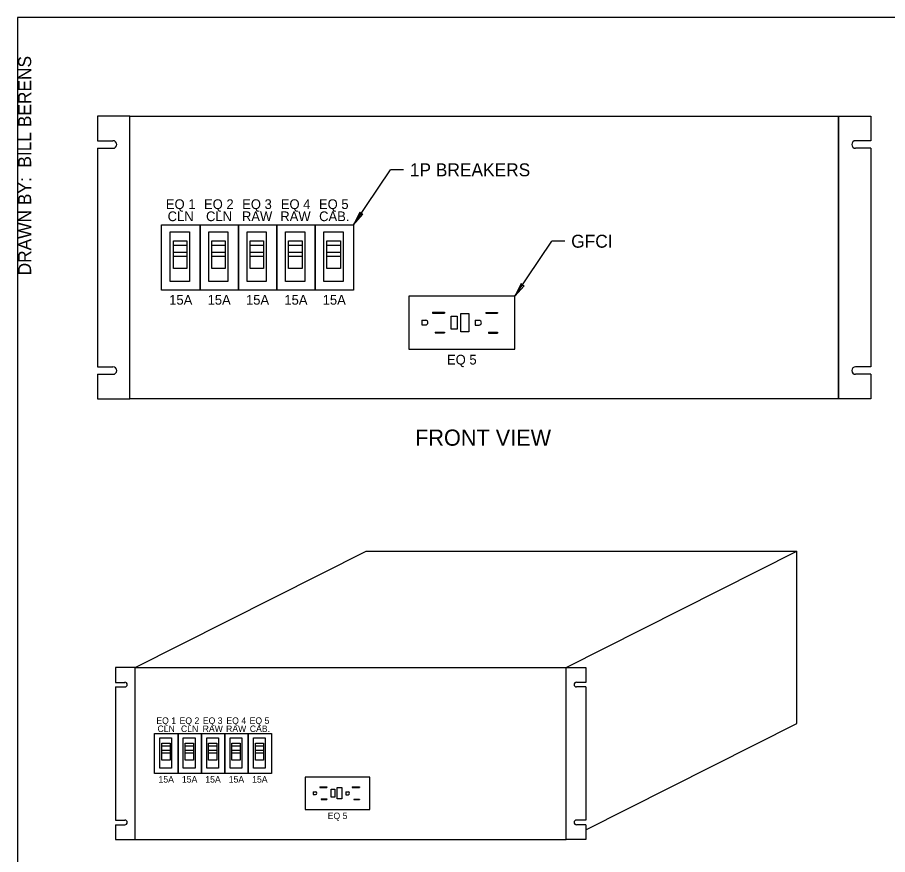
# Model space of a CAD drawing. Extents: x 99862 to 103680, y 99470 to 102076.
# Drawn here: x 99862 to 100936, y 101041 to 102076 of the extents above; entities that cross this region are included whole.
import ezdxf

# ---------------------------------------------------------------- set-up
doc = ezdxf.new("R2010")
doc.units = 0
for name, color, linetype in [('Level 1', 7, 'Continuous'), ('Level 11', 7, 'Continuous'), ('Level 15', 7, 'Continuous'), ('Level 2', 7, 'Continuous'), ('Level 20', 7, 'Continuous'), ('Level 26', 7, 'Continuous'), ('Level 40', 7, 'Continuous'), ('Level 62', 7, 'Continuous'), ('TR_TS_TrafficSystemsUserLevel2New', 7, 'Continuous')]:
    doc.layers.add(name, color=color, linetype=linetype)

msp = doc.modelspace()

# ---------------------------------------------------------------- linework, layer by layer
at = {"layer": 'Level 1'}
msp.add_lwpolyline([(99862, 99999.5), (103151, 99999.5), (103151, 102075.5), (99862, 102075.5)], close=True, dxfattribs=at)
at = {"layer": 'Level 11'}
for p, q in [((100374.5, 101711.3), (100389.1, 101711.3)), ((100374.5, 101711.3), (100374.5, 101710.1)), ((100374.5, 101710.1), (100389.1, 101710.1)), ((100389.1, 101711.3), (100389.1, 101710.1)), ((100440.2, 101711.1), (100454.8, 101711.1)), ((100440.2, 101711.1), (100440.2, 101710)), ((100440.2, 101710), (100454.8, 101710)), ((100454.8, 101711.1), (100454.8, 101710)), ((100361.4, 101701.4), (100361.4, 101695.6)), ((100361.4, 101701.4), (100366.2, 101701.4)), ((100427.2, 101701.3), (100427.2, 101695.4)), ((100427.2, 101701.3), (100431.9, 101701.3)), ((100361.4, 101695.6), (100366, 101695.6)), ((100377.8, 101686.8), (100389.2, 101686.8)), ((100377.8, 101686.8), (100377.8, 101685.7)), ((100389.2, 101686.8), (100389.2, 101685.7)), ((100427.2, 101695.4), (100431.9, 101695.4)), ((100443.5, 101686.7), (100454.9, 101686.7)), ((100443.5, 101686.7), (100443.5, 101685.5)), ((100454.9, 101686.7), (100454.9, 101685.5)), ((100377.8, 101685.7), (100389.2, 101685.7)), ((100443.5, 101685.5), (100454.9, 101685.5)), ((100227.3, 101118.9), (100227.3, 101115.4)), ((100227.3, 101118.9), (100230.2, 101118.9)), ((100235.2, 101125), (100244.2, 101125)), ((100235.2, 101125), (100235.2, 101124.3)), ((100235.2, 101124.3), (100244.2, 101124.3)), ((100244.2, 101125), (100244.2, 101124.3)), ((100267.3, 101118.9), (100267.3, 101115.3)), ((100267.3, 101118.9), (100270.2, 101118.9)), ((100275.3, 101124.9), (100284.2, 101124.9)), ((100275.3, 101124.9), (100275.3, 101124.2)), ((100275.3, 101124.2), (100284.2, 101124.2)), ((100284.2, 101124.9), (100284.2, 101124.2)), ((100227.3, 101115.4), (100230.1, 101115.4)), ((100237.2, 101110.1), (100244.2, 101110.1)), ((100237.2, 101110.1), (100237.2, 101109.4)), ((100237.2, 101109.4), (100244.2, 101109.4)), ((100244.2, 101110.1), (100244.2, 101109.4)), ((100267.3, 101115.3), (100270.3, 101115.3)), ((100277.3, 101110), (100284.3, 101110)), ((100277.3, 101110), (100277.3, 101109.3)), ((100277.3, 101109.3), (100284.3, 101109.3)), ((100284.3, 101110), (100284.3, 101109.3))]:
    msp.add_line(p, q, dxfattribs=at)
for centre, radius, start, end in [((100366, 101698.5), 2.91, 269.7062, 86.4581), ((100431.9, 101698.3), 2.9, 271.1491, 89.3526), ((100230.1, 101117.2), 1.77, 269.7062, 86.4581), ((100270.2, 101117.1), 1.77, 271.1491, 89.3526)]:
    msp.add_arc(centre, radius, start, end, dxfattribs=at)
at = {"layer": 'Level 15'}
for p, q in [((100277, 101819.3), (100322.5, 101887.2)), ((100338.5, 101887.2), (100322.5, 101887.2)), ((100476.2, 101731.1), (100521.7, 101799)), ((100537.7, 101799), (100521.7, 101799))]:
    msp.add_line(p, q, dxfattribs=at)
for points in [[(100277, 101819.3), (100288.4, 101832.3), (100286.1, 101832.9), (100284.7, 101834.8)], [(100476.2, 101731.1), (100487.6, 101744.1), (100485.3, 101744.7), (100483.9, 101746.6)]]:
    msp.add_lwpolyline(points, close=True, dxfattribs=at)
at = {"layer": 'Level 2'}
for p, q in [((100054.6, 101780.4), (100071.2, 101780.4)), ((100102, 101780.4), (100118.6, 101780.4)), ((100149.4, 101780.4), (100166, 101780.4)), ((100196.8, 101780.4), (100213.4, 101780.4)), ((100244.2, 101780.4), (100260.8, 101780.4)), ((100040.3, 101167.1), (100050.4, 101167.1)), ((100069.1, 101167.1), (100079.3, 101167.1)), ((100098, 101167.1), (100108.1, 101167.1)), ((100126.9, 101167.1), (100137, 101167.1)), ((100155.8, 101167.1), (100165.9, 101167.1))]:
    msp.add_line(p, q, dxfattribs=at)
for points in [[(100040.1, 101819.3), (100087.5, 101819.3), (100087.5, 101738.4), (100040.1, 101738.4)], [(100087.5, 101819.3), (100134.9, 101819.3), (100134.9, 101738.4), (100087.5, 101738.4)], [(100134.9, 101819.3), (100182.2, 101819.3), (100182.2, 101738.4), (100134.9, 101738.4)], [(100182.2, 101819.3), (100229.6, 101819.3), (100229.6, 101738.4), (100182.2, 101738.4)], [(100229.6, 101819.3), (100277, 101819.3), (100277, 101738.4), (100229.6, 101738.4)], [(100050.8, 101810.8), (100074.6, 101810.8), (100074.6, 101749.3), (100050.8, 101749.3)], [(100098.2, 101810.8), (100122, 101810.8), (100122, 101749.3), (100098.2, 101749.3)], [(100145.6, 101810.8), (100169.3, 101810.8), (100169.3, 101749.3), (100145.6, 101749.3)], [(100193, 101810.8), (100216.7, 101810.8), (100216.7, 101749.3), (100193, 101749.3)], [(100240.4, 101810.8), (100264.1, 101810.8), (100264.1, 101749.3), (100240.4, 101749.3)], [(100054.6, 101799.7), (100071.2, 101799.7), (100071.2, 101765.5), (100054.6, 101765.5)], [(100054.6, 101794.3), (100071.2, 101794.3), (100071.2, 101785.2), (100054.6, 101785.2)], [(100102, 101799.7), (100118.6, 101799.7), (100118.6, 101765.5), (100102, 101765.5)], [(100102, 101794.3), (100118.6, 101794.3), (100118.6, 101785.2), (100102, 101785.2)], [(100149.4, 101799.7), (100166, 101799.7), (100166, 101765.5), (100149.4, 101765.5)], [(100149.4, 101794.3), (100166, 101794.3), (100166, 101785.2), (100149.4, 101785.2)], [(100196.8, 101799.7), (100213.4, 101799.7), (100213.4, 101765.5), (100196.8, 101765.5)], [(100196.8, 101794.3), (100213.4, 101794.3), (100213.4, 101785.2), (100196.8, 101785.2)], [(100244.2, 101799.7), (100260.8, 101799.7), (100260.8, 101765.5), (100244.2, 101765.5)], [(100244.2, 101794.3), (100260.8, 101794.3), (100260.8, 101785.2), (100244.2, 101785.2)], [(100031.4, 101190.8), (100060.3, 101190.8), (100060.3, 101141.5), (100031.4, 101141.5)], [(100038, 101185.7), (100052.4, 101185.7), (100052.4, 101148.2), (100038, 101148.2)], [(100060.3, 101190.8), (100089.2, 101190.8), (100089.2, 101141.5), (100060.3, 101141.5)], [(100066.8, 101185.7), (100081.3, 101185.7), (100081.3, 101148.2), (100066.8, 101148.2)], [(100089.2, 101190.8), (100118.1, 101190.8), (100118.1, 101141.5), (100089.2, 101141.5)], [(100095.7, 101185.7), (100110.2, 101185.7), (100110.2, 101148.2), (100095.7, 101148.2)], [(100118.1, 101190.8), (100146.9, 101190.8), (100146.9, 101141.5), (100118.1, 101141.5)], [(100124.6, 101185.7), (100139.1, 101185.7), (100139.1, 101148.2), (100124.6, 101148.2)], [(100146.9, 101190.8), (100175.8, 101190.8), (100175.8, 101141.5), (100146.9, 101141.5)], [(100153.5, 101185.7), (100168, 101185.7), (100168, 101148.2), (100153.5, 101148.2)], [(100040.3, 101178.9), (100050.4, 101178.9), (100050.4, 101158), (100040.3, 101158)], [(100040.3, 101175.6), (100050.4, 101175.6), (100050.4, 101170), (100040.3, 101170)], [(100069.1, 101178.9), (100079.3, 101178.9), (100079.3, 101158), (100069.1, 101158)], [(100069.1, 101175.6), (100079.3, 101175.6), (100079.3, 101170), (100069.1, 101170)], [(100098, 101178.9), (100108.1, 101178.9), (100108.1, 101158), (100098, 101158)], [(100098, 101175.6), (100108.1, 101175.6), (100108.1, 101170), (100098, 101170)], [(100126.9, 101178.9), (100137, 101178.9), (100137, 101158), (100126.9, 101158)], [(100126.9, 101175.6), (100137, 101175.6), (100137, 101170), (100126.9, 101170)], [(100155.8, 101178.9), (100165.9, 101178.9), (100165.9, 101158), (100155.8, 101158)], [(100155.8, 101175.6), (100165.9, 101175.6), (100165.9, 101170), (100155.8, 101170)]]:
    msp.add_lwpolyline(points, close=True, dxfattribs=at)
at = {"layer": 'Level 26'}
for p, q in [((100007.5, 101272.5), (100292.5, 101416.2)), ((100292.5, 101416.2), (100824.4, 101416.2)), ((100539.4, 101272.5), (100824.4, 101416.2)), ((100824.4, 101203.4), (100824.4, 101416.2)), ((100007.5, 101059.8), (100007.5, 101272.5)), ((100007.5, 101272.5), (100539.4, 101272.5)), ((100007.5, 101059.8), (100007.5, 101272.5)), ((100539.4, 101059.8), (100539.4, 101272.5)), ((100563.7, 101072.1), (100824.4, 101203.4)), ((100007.5, 101059.8), (100539.4, 101059.8))]:
    msp.add_line(p, q, dxfattribs=at)
msp.add_lwpolyline([(100000.9, 101953.4), (100875.9, 101953.4), (100875.9, 101604.4), (100000.9, 101604.4)], close=True, dxfattribs=at)
at = {"layer": 'Level 40'}
for points in [[(100476.2, 101731.1), (100345.1, 101731.1), (100345.1, 101665.5), (100476.2, 101665.5)], [(100419.5, 101709.8), (100419.5, 101687.1), (100409.5, 101687.1), (100409.5, 101709.8)], [(100405.1, 101706.5), (100405.1, 101690.4), (100397.5, 101690.4), (100397.5, 101706.5)], [(100297.3, 101137.1), (100217.3, 101137.1), (100217.3, 101097.1), (100297.3, 101097.1)], [(100253.9, 101122), (100253.9, 101112.3), (100249.3, 101112.3), (100249.3, 101122)], [(100262.7, 101124.1), (100262.7, 101110.3), (100256.6, 101110.3), (100256.6, 101124.1)]]:
    msp.add_lwpolyline(points, close=True, dxfattribs=at)
at = {"layer": 'TR_TS_TrafficSystemsUserLevel2New'}
for p, q in [((99961, 101923.2), (99979.9, 101923.2)), ((100915.8, 101923.2), (100896.9, 101923.2)), ((99961, 101913.8), (99979.9, 101913.8)), ((100915.8, 101913.8), (100896.9, 101913.8)), ((99961, 101644), (99979.9, 101644)), ((100915.8, 101644), (100896.9, 101644)), ((99961, 101634.6), (99979.9, 101634.6)), ((100915.8, 101634.6), (100896.9, 101634.6)), ((99983.2, 101254.1), (99994.7, 101254.1)), ((99983.2, 101248.4), (99994.7, 101248.4)), ((100563.7, 101254.1), (100552.2, 101254.1)), ((100563.7, 101248.4), (100552.2, 101248.4)), ((99983.2, 101083.9), (99994.7, 101083.9)), ((99983.2, 101078.2), (99994.7, 101078.2)), ((100563.7, 101083.9), (100552.2, 101083.9)), ((100563.7, 101078.2), (100552.2, 101078.2))]:
    msp.add_line(p, q, dxfattribs=at)
for points in [[(99961, 101634.6), (99961, 101604.4), (100000.9, 101604.4), (100000.9, 101953.4), (99961, 101953.4), (99961, 101923.2)], [(100915.8, 101634.6), (100915.8, 101604.4), (100875.9, 101604.4), (100875.9, 101953.4), (100915.8, 101953.4), (100915.8, 101923.2)], [(99961, 101913.8), (99961, 101644)], [(100915.8, 101913.8), (100915.8, 101644)], [(99983.2, 101078.2), (99983.2, 101059.8), (100007.5, 101059.8), (100007.5, 101272.5), (99983.2, 101272.5), (99983.2, 101254.1)], [(100563.7, 101078.2), (100563.7, 101059.8), (100539.4, 101059.8), (100539.4, 101272.5), (100563.7, 101272.5), (100563.7, 101254.1)], [(99983.2, 101248.4), (99983.2, 101083.9)], [(100563.7, 101248.4), (100563.7, 101083.9)]]:
    msp.add_lwpolyline(points, dxfattribs=at)
for centre, radius, start, end in [((99979.9, 101918.5), 4.71, 270, 90), ((100896.9, 101918.5), 4.71, 90, 270), ((99979.9, 101639.3), 4.71, 270, 90), ((100896.9, 101639.3), 4.71, 90, 270), ((99994.7, 101251.3), 2.87, 270, 90), ((100552.2, 101251.3), 2.87, 90, 270), ((99994.7, 101081.1), 2.87, 270, 90), ((100552.2, 101081.1), 2.87, 90, 270)]:
    msp.add_arc(centre, radius, start, end, dxfattribs=at)

# ---------------------------------------------------------------- texts
at = {"layer": 'Level 20'}
for s, height, p in [('1P BREAKERS', 16, (100346.5, 101879.2)), ('EQ 1', 12, (100045.3, 101838.8)), ('EQ 2', 12, (100092.4, 101838.8)), ('EQ 3', 12, (100139.5, 101838.8)), ('EQ 4', 12, (100187.2, 101838.8)), ('EQ 5', 12, (100234.3, 101838.8)), ('CLN', 12, (100047.5, 101823.8)), ('CLN', 12, (100094.9, 101823.8)), ('RAW', 12, (100139.2, 101823.8)), ('RAW', 12, (100186.6, 101823.8)), ('CAB.', 12, (100234.5, 101823.8)), ('GFCI', 16, (100545.7, 101791)), ('15A', 12, (100049.4, 101720.6)), ('15A', 12, (100096.8, 101720.6)), ('15A', 12, (100144.2, 101720.6)), ('15A', 12, (100191.6, 101720.6)), ('15A', 12, (100238.9, 101720.6)), ('EQ 5', 12, (100392.4, 101646.7)), ('FRONT VIEW', 20, (100353, 101546.4)), ('EQ 1', 8, (100033.5, 101202.8)), ('EQ 2', 8, (100062.2, 101202.8)), ('EQ 3', 8, (100090.9, 101202.8)), ('EQ 4', 8, (100120, 101202.8)), ('EQ 5', 8, (100148.7, 101202.8)), ('CLN', 8, (100035, 101192.8)), ('CLN', 8, (100063.9, 101192.8)), ('RAW', 8, (100090.7, 101192.8)), ('RAW', 8, (100119.6, 101192.8)), ('CAB.', 8, (100148.9, 101192.8)), ('15A', 8, (100036.2, 101130.3)), ('15A', 8, (100065.1, 101130.3)), ('15A', 8, (100094, 101130.3)), ('15A', 8, (100122.9, 101130.3)), ('15A', 8, (100151.8, 101130.3)), ('EQ 5', 8, (100245.1, 101085.2))]:
    msp.add_text(s, height=height, dxfattribs=at).set_placement(p)
at = {"layer": 'Level 62'}
msp.add_text('DRAWN BY:  BILL BERENS', height=16, rotation=90, dxfattribs=at).set_placement((99879, 101756.8))

doc.saveas('drawing.dxf')
